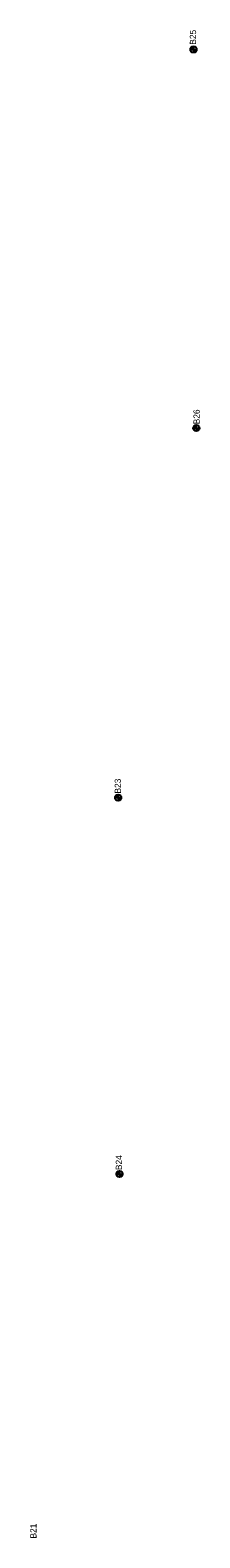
# Model space of a CAD drawing. Extents: x 327762 to 372792, y 127949 to 259367.
# Drawn here: x 361453 to 361723, y 140358 to 142767 of the extents above; entities that cross this region are included whole.
import ezdxf

# ---------------------------------------------------------------- set-up
doc = ezdxf.new("R2010")
doc.units = 0
for name, color, linetype in [('E_SOIL_BORE1 [KAPUR_CADDS_LEVELS]', 7, 'Continuous'), ('E_SOIL_BORE2 [KAPUR_CADDS_LEVELS]', 7, 'Continuous'), ('P_MARK', 7, 'Continuous')]:
    doc.layers.add(name, color=color, linetype=linetype)

msp = doc.modelspace()

# ---------------------------------------------------------------- linework, layer by layer
at = {"layer": 'P_MARK'}
for p, q in [((361713.4, 142741.6), (361713.4, 142731.6)), ((361708.4, 142736.6), (361718.4, 142736.6)), ((361717.8, 142136.6), (361717.8, 142126.6)), ((361712.8, 142131.6), (361722.8, 142131.6)), ((361588.1, 141541), (361598.1, 141541)), ((361593.1, 141546), (361593.1, 141536)), ((361590.2, 140939.4), (361600.2, 140939.3)), ((361595.2, 140944.3), (361595.2, 140934.4))]:
    msp.add_line(p, q, dxfattribs=at)
for centre in [(361713.4, 142736.6), (361717.8, 142131.6), (361593.1, 141541), (361595.2, 140939.4)]:
    msp.add_circle(centre, 5, dxfattribs=at)
for centre, radius, start, end in [((361713.4, 142736.6), 4.5, 89.9869, 179.9869), ((361713.4, 142736.6), 4, 89.9869, 179.9869), ((361713.4, 142736.6), 3.5, 89.9869, 179.9869), ((361713.4, 142736.6), 3, 89.9869, 179.9869), ((361713.4, 142736.6), 2.5, 89.9869, 179.9869), ((361713.4, 142736.6), 2, 89.9869, 179.9869), ((361713.4, 142736.6), 1.5, 89.9869, 179.9869), ((361713.4, 142736.6), 1, 89.9869, 179.9869), ((361713.4, 142736.6), 0.5, 89.9869, 179.9869), ((361713.4, 142736.6), 4.5, 269.9869, 359.9869), ((361713.4, 142736.6), 4, 269.9869, 359.9869), ((361713.4, 142736.6), 3.5, 269.9869, 359.9869), ((361713.4, 142736.6), 3, 269.9869, 359.9869), ((361713.4, 142736.6), 2.5, 269.9869, 359.9869), ((361713.4, 142736.6), 2, 269.9869, 359.9869), ((361713.4, 142736.6), 1.5, 269.9869, 359.9869), ((361713.4, 142736.6), 1, 269.9869, 359.9869), ((361713.4, 142736.6), 0.5, 269.9869, 359.9869), ((361717.8, 142131.6), 4.5, 89.9869, 179.9869), ((361717.8, 142131.6), 4, 89.9869, 179.9869), ((361717.8, 142131.6), 3.5, 89.9869, 179.9869), ((361717.8, 142131.6), 3, 89.9869, 179.9869), ((361717.8, 142131.6), 2.5, 89.9869, 179.9869), ((361717.8, 142131.6), 2, 89.9869, 179.9869), ((361717.8, 142131.6), 1.5, 89.9869, 179.9869), ((361717.8, 142131.6), 1, 89.9869, 179.9869), ((361717.8, 142131.6), 0.5, 89.9869, 179.9869), ((361717.8, 142131.6), 4.5, 269.9869, 359.9869), ((361717.8, 142131.6), 4, 269.9869, 359.9869), ((361717.8, 142131.6), 3.5, 269.9869, 359.9869), ((361717.8, 142131.6), 3, 269.9869, 359.9869), ((361717.8, 142131.6), 2.5, 269.9869, 359.9869), ((361717.8, 142131.6), 2, 269.9869, 359.9869), ((361717.8, 142131.6), 1.5, 269.9869, 359.9869), ((361717.8, 142131.6), 1, 269.9869, 359.9869), ((361717.8, 142131.6), 0.5, 269.9869, 359.9869), ((361593.1, 141541), 4.5, 89.9869, 179.9869), ((361593.1, 141541), 4, 89.9869, 179.9869), ((361593.1, 141541), 3.5, 89.9869, 179.9869), ((361593.1, 141541), 3, 89.9869, 179.9869), ((361593.1, 141541), 2.5, 89.9869, 179.9869), ((361593.1, 141541), 2, 89.9869, 179.9869), ((361593.1, 141541), 1.5, 89.9869, 179.9869), ((361593.1, 141541), 1, 89.9869, 179.9869), ((361593.1, 141541), 0.5, 89.9869, 179.9869), ((361593.1, 141541), 4.5, 269.9869, 359.9869), ((361593.1, 141541), 4, 269.9869, 359.9869), ((361593.1, 141541), 3.5, 269.9869, 359.9869), ((361593.1, 141541), 3, 269.9869, 359.9869), ((361593.1, 141541), 2.5, 269.9869, 359.9869), ((361593.1, 141541), 2, 269.9869, 359.9869), ((361593.1, 141541), 1.5, 269.9869, 359.9869), ((361593.1, 141541), 1, 269.9869, 359.9869), ((361593.1, 141541), 0.5, 269.9869, 359.9869), ((361595.2, 140939.4), 4.5, 89.9869, 179.9869), ((361595.2, 140939.4), 4, 89.9869, 179.9869), ((361595.2, 140939.4), 3.5, 89.9869, 179.9869), ((361595.2, 140939.4), 3, 89.9869, 179.9869), ((361595.2, 140939.4), 2.5, 89.9869, 179.9869), ((361595.2, 140939.4), 2, 89.9869, 179.9869), ((361595.2, 140939.4), 1.5, 89.9869, 179.9869), ((361595.2, 140939.4), 1, 89.9869, 179.9869), ((361595.2, 140939.4), 0.5, 89.9869, 179.9869), ((361595.2, 140939.4), 4.5, 269.9869, 359.9869), ((361595.2, 140939.4), 4, 269.9869, 359.9869), ((361595.2, 140939.4), 3.5, 269.9869, 359.9869), ((361595.2, 140939.4), 3, 269.9869, 359.9869), ((361595.2, 140939.4), 2.5, 269.9869, 359.9869), ((361595.2, 140939.4), 2, 269.9869, 359.9869), ((361595.2, 140939.4), 1.5, 269.9869, 359.9869), ((361595.2, 140939.4), 1, 269.9869, 359.9869), ((361595.2, 140939.4), 0.5, 269.9869, 359.9869)]:
    msp.add_arc(centre, radius, start, end, dxfattribs=at)

# ---------------------------------------------------------------- texts
at = {"layer": 'E_SOIL_BORE1 [KAPUR_CADDS_LEVELS]'}
for s, p in [('B23', (361597.4, 141547.5)), ('B24', (361599.1, 140945.7))]:
    msp.add_text(s, height=10, rotation=89.9869, dxfattribs=at).set_placement(p)
at = {"layer": 'E_SOIL_BORE2 [KAPUR_CADDS_LEVELS]'}
for s, p in [('B25', (361717.5, 142744.2)), ('B26', (361723.3, 142137.6)), ('B21', (361462.7, 140356.9))]:
    msp.add_text(s, height=10, rotation=89.9869, dxfattribs=at).set_placement(p)

doc.saveas('drawing.dxf')
